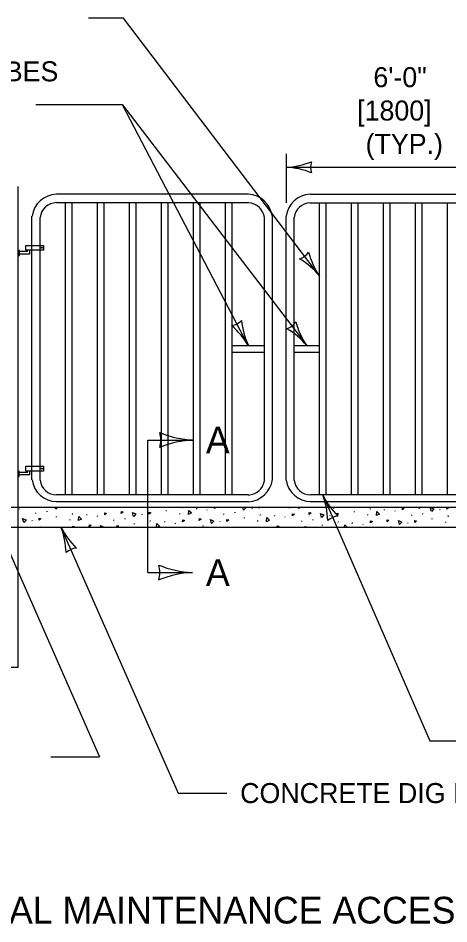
# Model space of a CAD drawing. Extents: x 49991.4 to 50021, y 49987.6 to 50011.4.
# Drawn here: x 50001.949 to 50003.24, y 49992.169 to 49994.882 of the extents above; entities that cross this region are included whole.
import ezdxf

# ---------------------------------------------------------------- set-up
doc = ezdxf.new("R2010")
doc.units = 0
for name, color, linetype in [('Level 1', 7, 'Continuous'), ('Level 2', 7, 'Continuous'), ('Level 3', 7, 'Continuous'), ('Level 4', 7, 'Continuous'), ('Level 6', 7, 'Continuous')]:
    doc.layers.add(name, color=color, linetype=linetype)

msp = doc.modelspace()

# ---------------------------------------------------------------- linework, layer by layer
at = {"layer": 'Level 1'}
for p, q in [((50001.9492, 49993.4177), (50001.9492, 49994.3778)), ((50002.639, 49994.3543), (50002.0642, 49994.3544)), ((50002.8238, 49994.3543), (50003.3985, 49994.3543)), ((50002.6391, 49994.3293), (50002.0641, 49994.3293)), ((50002.0908, 49993.4537), (50002.0908, 49994.3293)), ((50002.1108, 49993.4537), (50002.1108, 49994.3293)), ((50002.1868, 49993.4537), (50002.1868, 49994.3293)), ((50002.2068, 49993.4537), (50002.2068, 49994.3293)), ((50002.2828, 49993.4537), (50002.2828, 49994.3293)), ((50002.3028, 49993.4537), (50002.3028, 49994.3293)), ((50002.3788, 49993.4537), (50002.3788, 49994.3293)), ((50002.3988, 49993.4537), (50002.3988, 49994.3293)), ((50002.4748, 49993.4537), (50002.4748, 49994.3293)), ((50002.4948, 49993.4537), (50002.4948, 49994.3293)), ((50002.5708, 49993.4537), (50002.5708, 49994.3293)), ((50002.5908, 49993.4537), (50002.5908, 49994.3293)), ((50002.8236, 49994.3293), (50003.3985, 49994.3293)), ((50002.8519, 49993.4537), (50002.8519, 49994.3293)), ((50002.8719, 49993.4537), (50002.8719, 49994.3293)), ((50002.9479, 49993.4537), (50002.9479, 49994.3293)), ((50002.9679, 49993.4537), (50002.9679, 49994.3293)), ((50003.0439, 49993.4537), (50003.0439, 49994.3293)), ((50003.0639, 49993.4537), (50003.0639, 49994.3293)), ((50003.1399, 49993.4537), (50003.1399, 49994.3293)), ((50003.1599, 49993.4537), (50003.1599, 49994.3293)), ((50003.2359, 49993.4537), (50003.2359, 49994.3293)), ((50001.9908, 49993.4993), (50001.9908, 49994.2888)), ((50002.0148, 49993.4978), (50002.0148, 49994.2853)), ((50002.6868, 49993.4957), (50002.6868, 49994.2853)), ((50002.7108, 49993.4999), (50002.7108, 49994.2888)), ((50002.7519, 49993.4986), (50002.7519, 49994.2888)), ((50002.7759, 49993.498), (50002.7759, 49994.2853)), ((50001.9722, 49994.1866), (50001.9722, 49994.2014)), ((50001.9722, 49994.2014), (50002.0252, 49994.2014)), ((50002.0252, 49994.2014), (50002.0252, 49994.1866)), ((50001.953, 49994.1864), (50001.9492, 49994.1864)), ((50001.9773, 49994.1827), (50001.9492, 49994.1827)), ((50001.9848, 49994.1752), (50001.9492, 49994.1752)), ((50001.9492, 49994.171), (50001.953, 49994.171)), ((50001.953, 49994.171), (50001.953, 49994.1864)), ((50002.0252, 49994.1866), (50001.9722, 49994.1866)), ((50001.9773, 49994.1827), (50001.9773, 49994.1866)), ((50001.9848, 49994.1752), (50001.9848, 49994.1866)), ((50002.5908, 49993.9015), (50002.6868, 49993.9015)), ((50002.7759, 49993.9015), (50002.8519, 49993.9015)), ((50002.5908, 49993.8815), (50002.6868, 49993.8815)), ((50002.7759, 49993.8815), (50002.8519, 49993.8815)), ((50001.9773, 49993.5211), (50001.9492, 49993.5211)), ((50001.9773, 49993.5211), (50001.9773, 49993.525)), ((50001.9848, 49993.5136), (50001.9848, 49993.525)), ((50001.9848, 49993.5136), (50001.9492, 49993.5136)), ((50002.6389, 49993.4537), (50002.0641, 49993.4537)), ((50003.4, 49993.4537), (50002.8253, 49993.4537)), ((49999.9385, 49993.4177), (50005.4753, 49993.4177)), ((50001.952, 49993.4125), (50001.9533, 49993.4116)), ((50002.6389, 49993.4337), (50002.0642, 49993.4337)), ((50002.0862, 49993.4177), (50002.0872, 49993.416)), ((50002.332, 49993.4168), (50002.3321, 49993.4177)), ((50002.4397, 49993.416), (50002.441, 49993.4151)), ((50002.4407, 49993.4159), (50002.442, 49993.415)), ((50002.4844, 49993.4117), (50002.4844, 49993.4139)), ((50002.6489, 49993.4145), (50002.6499, 49993.4127)), ((50002.7633, 49993.4145), (50002.7634, 49993.4167)), ((50003.4, 49993.4337), (50002.8253, 49993.4337)), ((50002.8947, 49993.4136), (50002.8948, 49993.4158)), ((50003.0024, 49993.4128), (50003.0037, 49993.4119)), ((50003.0034, 49993.4127), (50003.0047, 49993.4118)), ((50003.2116, 49993.4112), (50003.2126, 49993.4095)), ((50002.0028, 49993.3986), (50002.0028, 49993.4007)), ((50002.0366, 49993.403), (50002.0366, 49993.4051)), ((50002.0644, 49993.3873), (50002.0644, 49993.3895)), ((50002.1105, 49993.3978), (50002.1118, 49993.3969)), ((50002.1114, 49993.3976), (50002.1127, 49993.3968)), ((50002.1551, 49993.3935), (50002.1552, 49993.3956)), ((50002.1854, 49993.391), (50002.1867, 49993.3902)), ((50002.3196, 49993.3962), (50002.3206, 49993.3945)), ((50002.3937, 49993.4056), (50002.3937, 49993.4077)), ((50002.4341, 49993.3963), (50002.4341, 49993.3984)), ((50002.5147, 49993.4093), (50002.516, 49993.4084)), ((50002.5655, 49993.3954), (50002.5655, 49993.3975)), ((50002.5993, 49993.3998), (50002.5993, 49993.4019)), ((50002.6271, 49993.3841), (50002.6271, 49993.3863)), ((50002.6732, 49993.3945), (50002.6745, 49993.3937)), ((50002.6742, 49993.3944), (50002.6755, 49993.3936)), ((50002.7178, 49993.3903), (50002.7179, 49993.3924)), ((50002.7481, 49993.3878), (50002.7494, 49993.387)), ((50002.9564, 49993.4024), (50002.9564, 49993.4045)), ((50002.9968, 49993.3931), (50002.9968, 49993.3952)), ((50003.0471, 49993.4085), (50003.0472, 49993.4107)), ((50003.0774, 49993.4061), (50003.0787, 49993.4052)), ((50003.1282, 49993.3922), (50003.1282, 49993.3943)), ((50003.162, 49993.3966), (50003.162, 49993.3987)), ((50003.2359, 49993.3913), (50003.2372, 49993.3905)), ((50003.2369, 49993.3912), (50003.2382, 49993.3903)), ((50001.8892, 49993.3577), (50003.5733, 49993.3577)), ((50001.9904, 49993.378), (50001.9913, 49993.3763)), ((50002.0146, 49993.3581), (50002.0151, 49993.3577)), ((50002.0156, 49993.3579), (50002.0159, 49993.3577)), ((50002.1048, 49993.378), (50002.1049, 49993.3802)), ((50002.2362, 49993.3771), (50002.2363, 49993.3793)), ((50002.27, 49993.3815), (50002.2701, 49993.3837)), ((50002.2978, 49993.3659), (50002.2979, 49993.368)), ((50002.3383, 49993.3577), (50002.3383, 49993.3587)), ((50002.3439, 49993.3763), (50002.3452, 49993.3754)), ((50002.3449, 49993.3762), (50002.3462, 49993.3753)), ((50002.3886, 49993.372), (50002.3886, 49993.3742)), ((50002.4189, 49993.3696), (50002.4202, 49993.3687)), ((50002.4697, 49993.3577), (50002.4697, 49993.3578)), ((50002.5034, 49993.3601), (50002.5035, 49993.3622)), ((50002.5531, 49993.3748), (50002.554, 49993.373)), ((50002.6675, 49993.3748), (50002.6676, 49993.377)), ((50002.7989, 49993.3739), (50002.799, 49993.3761)), ((50002.8327, 49993.3783), (50002.8328, 49993.3805)), ((50002.8605, 49993.3627), (50002.8606, 49993.3648)), ((50002.9066, 49993.3731), (50002.9079, 49993.3722)), ((50002.9076, 49993.373), (50002.9089, 49993.3721)), ((50002.9513, 49993.3688), (50002.9513, 49993.371)), ((50002.9816, 49993.3664), (50002.9829, 49993.3655)), ((50003.0662, 49993.3577), (50003.0662, 49993.359)), ((50003.1158, 49993.3716), (50003.1167, 49993.3698)), ((50003.1898, 49993.3809), (50003.1899, 49993.383)), ((50003.2302, 49993.3716), (50003.2303, 49993.3737))]:
    msp.add_line(p, q, dxfattribs=at)
for points in [[(50001.9492, 49993.5248), (50001.9492, 49993.5093), (50001.9528, 49993.5093), (50001.9528, 49993.5248)], [(50001.9722, 49993.525), (50001.9722, 49993.5397), (50002.0252, 49993.5397), (50002.0252, 49993.525)]]:
    msp.add_lwpolyline(points, close=True, dxfattribs=at)
for points in [[(50001.9752, 49993.416), (50001.9753, 49993.4177)], [(50001.9772, 49993.4177), (50001.9752, 49993.416)], [(50002.0618, 49993.411), (50002.06, 49993.4177)], [(50002.068, 49993.4177), (50002.0619, 49993.4112)], [(50002.1077, 49993.4175), (50002.1077, 49993.4177)], [(50002.108, 49993.4177), (50002.1077, 49993.4175)], [(50002.2262, 49993.4166), (50002.2263, 49993.4177)], [(50002.2284, 49993.4177), (50002.2264, 49993.4167)], [(50002.5379, 49993.4128), (50002.5381, 49993.4177)], [(50002.5423, 49993.4177), (50002.5434, 49993.4174), (50002.5379, 49993.4128)], [(50002.5876, 49993.4167), (50002.5877, 49993.4177)], [(50002.5889, 49993.4177), (50002.5876, 49993.4167)], [(50002.6245, 49993.4078), (50002.6219, 49993.4177)], [(50002.6263, 49993.4177), (50002.6315, 49993.4155), (50002.6246, 49993.4079)], [(50002.6704, 49993.4142), (50002.6706, 49993.4177)], [(50002.6746, 49993.4177), (50002.6704, 49993.4142)], [(50002.7889, 49993.4134), (50002.7893, 49993.4177)], [(50002.7973, 49993.4177), (50002.7891, 49993.4135)], [(50003.1006, 49993.4096), (50003.1009, 49993.4156), (50003.1061, 49993.4142), (50003.1006, 49993.4096)], [(50003.1504, 49993.4134), (50003.1506, 49993.4177)], [(50003.1555, 49993.4177), (50003.1504, 49993.4134)], [(50003.1872, 49993.4046), (50003.184, 49993.4167), (50003.1943, 49993.4122), (50003.1873, 49993.4047)], [(50003.2331, 49993.411), (50003.2334, 49993.417), (50003.2387, 49993.4157), (50003.2331, 49993.411)], [(50002.0119, 49993.3778), (50002.0122, 49993.3838), (50002.0174, 49993.3824), (50002.0119, 49993.3778)], [(50002.1304, 49993.3769), (50002.1315, 49993.3893), (50002.1396, 49993.3817), (50002.1306, 49993.377)], [(50002.2086, 49993.3945), (50002.2089, 49993.4005), (50002.2142, 49993.3992), (50002.2086, 49993.3945)], [(50002.2584, 49993.3984), (50002.2587, 49993.4044), (50002.2639, 49993.4031), (50002.2584, 49993.3984)], [(50002.2952, 49993.3896), (50002.292, 49993.4016), (50002.3023, 49993.3972), (50002.2954, 49993.3897)], [(50002.3411, 49993.396), (50002.3415, 49993.402), (50002.3467, 49993.4007), (50002.3411, 49993.396)], [(50002.4596, 49993.3951), (50002.4608, 49993.4076), (50002.4689, 49993.3999), (50002.4598, 49993.3952)], [(50002.6931, 49993.3737), (50002.6942, 49993.3861), (50002.7023, 49993.3785), (50002.6933, 49993.3738)], [(50002.7713, 49993.3913), (50002.7716, 49993.3973), (50002.7769, 49993.396), (50002.7713, 49993.3913)], [(50002.8211, 49993.3952), (50002.8214, 49993.4012), (50002.8267, 49993.3999), (50002.8211, 49993.3952)], [(50002.8579, 49993.3863), (50002.8548, 49993.3984), (50002.865, 49993.394), (50002.8581, 49993.3865)], [(50002.9038, 49993.3928), (50002.9042, 49993.3988), (50002.9094, 49993.3974), (50002.9038, 49993.3928)], [(50003.0223, 49993.3919), (50003.0235, 49993.4044), (50003.0316, 49993.3967), (50003.0225, 49993.392)], [(50001.9659, 49993.3713), (50001.9628, 49993.3834), (50001.973, 49993.379), (50001.9661, 49993.3715)], [(50002.1129, 49993.3577), (50002.1131, 49993.3608), (50002.1183, 49993.3595), (50002.1162, 49993.3577)], [(50002.1625, 49993.3587), (50002.1629, 49993.3647), (50002.1681, 49993.3634), (50002.1625, 49993.3587)], [(50002.1973, 49993.3577), (50002.1962, 49993.3619), (50002.206, 49993.3577)], [(50002.2454, 49993.3577), (50002.2456, 49993.3623), (50002.2509, 49993.361), (50002.247, 49993.3577)], [(50002.364, 49993.3577), (50002.365, 49993.3679), (50002.3731, 49993.3602), (50002.3682, 49993.3577)], [(50002.442, 49993.3731), (50002.4424, 49993.3791), (50002.4476, 49993.3777), (50002.442, 49993.3731)], [(50002.4918, 49993.377), (50002.4921, 49993.383), (50002.4974, 49993.3816), (50002.4918, 49993.377)], [(50002.5286, 49993.3681), (50002.5255, 49993.3802), (50002.5357, 49993.3758), (50002.5288, 49993.3682)], [(50002.5746, 49993.3746), (50002.5749, 49993.3805), (50002.5801, 49993.3792), (50002.5746, 49993.3746)], [(50002.7254, 49993.3577), (50002.7256, 49993.3615), (50002.7308, 49993.3602), (50002.7279, 49993.3577)], [(50002.7592, 49993.3577), (50002.7589, 49993.3587), (50002.7613, 49993.3577)], [(50002.8083, 49993.3577), (50002.8083, 49993.3591), (50002.8136, 49993.3577), (50002.8135, 49993.3577)], [(50002.927, 49993.3577), (50002.9277, 49993.3647), (50002.935, 49993.3577)], [(50003.0047, 49993.3699), (50003.0051, 49993.3759), (50003.0103, 49993.3745), (50003.0047, 49993.3699)], [(50003.0545, 49993.3737), (50003.0548, 49993.3797), (50003.0601, 49993.3784), (50003.0545, 49993.3737)], [(50003.0913, 49993.3649), (50003.0882, 49993.377), (50003.0984, 49993.3725), (50003.0915, 49993.365)], [(50003.1373, 49993.3713), (50003.1376, 49993.3773), (50003.1429, 49993.376), (50003.1373, 49993.3713)]]:
    msp.add_lwpolyline(points, dxfattribs=at)
for centre in [(50002.0202, 49994.1943), (50002.0202, 49993.5327)]:
    msp.add_circle(centre, 0.00125, dxfattribs=at)
for centre, radius, start, end in [((50002.0663, 49994.2782), 0.0762, 91.5229, 171.9742), ((50002.6353, 49994.2782), 0.0762, 8.0258, 87.2614), ((50002.8274, 49994.2782), 0.0762, 92.7386, 171.9742), ((50002.0655, 49994.2782), 0.0512, 91.5229, 171.9742), ((50002.6361, 49994.2782), 0.0512, 8.0258, 86.6578), ((50002.8266, 49994.2782), 0.0512, 93.3422, 171.9742), ((50002.0663, 49993.5099), 0.0762, 188.0258, 268.4771), ((50002.0655, 49993.5049), 0.0512, 188.0258, 268.4771), ((50002.6352, 49993.5098), 0.0762, 272.7386, 352.5107), ((50002.6364, 49993.5048), 0.0512, 272.7386, 349.801), ((50002.8273, 49993.5099), 0.0762, 188.5288, 268.4771), ((50002.8266, 49993.5049), 0.0512, 187.7401, 268.4771)]:
    msp.add_arc(centre, radius, start, end, dxfattribs=at)
at = {"layer": 'Level 3'}
for p, q in [((50002.2652, 49994.8821), (50002.1604, 49994.8821)), ((50002.8519, 49994.1104), (50002.2652, 49994.8821)), ((50002.2624, 49994.6227), (50002.0021, 49994.6227)), ((50002.6388, 49993.9015), (50002.2624, 49994.6227)), ((50002.2624, 49994.6227), (50002.8139, 49993.9015)), ((50002.7519, 49994.4753), (50002.7519, 49994.3288)), ((50002.7519, 49994.4353), (50003.472, 49994.4353)), ((50002.8617, 49993.4537), (50003.1823, 49992.7172)), ((50002.8824, 49993.393), (50002.8833, 49993.3913)), ((50001.8892, 49993.3577), (50002.1928, 49992.6694)), ((50002.0775, 49993.3577), (50002.429, 49992.5608)), ((50003.1823, 49992.7172), (50003.3277, 49992.7172)), ((50002.0474, 49992.6694), (50002.1928, 49992.6694)), ((50002.429, 49992.5608), (50002.5744, 49992.5608))]:
    msp.add_line(p, q, dxfattribs=at)
for centre, radius, start, end in [((50002.7404, 49994.668), 0.233, 272.8273, 292.0772), ((50002.8801, 49994.4353), 0.0548, 162.1388, 197.8612), ((50002.7428, 49994.2132), 0.2223, 67.456, 87.6395), ((50002.7743, 49994.2125), 0.0548, 289.3851, 325.1074), ((50003.0343, 49994.2375), 0.2223, 194.7022, 214.8858), ((50002.6736, 49993.9604), 0.233, 40.0735, 59.3234), ((50002.5795, 49994.0151), 0.0548, 279.7009, 315.4232), ((50002.4378, 49993.7836), 0.233, 30.3893, 49.6392), ((50002.84, 49993.9961), 0.2223, 185.018, 205.2016), ((50002.736, 49994.0033), 0.0548, 289.5454, 325.2678), ((50002.9959, 49994.0291), 0.2223, 194.8626, 215.0461), ((50002.6361, 49993.751), 0.233, 40.2339, 59.4838), ((50002.487, 49993.9146), 0.2964, 247.456, 267.6395), ((50002.3039, 49993.6184), 0.073, 342.1388, 17.8612), ((50002.4901, 49993.3082), 0.3107, 92.8273, 112.0772), ((50002.6544, 49993.3735), 0.2223, 0.9771, 21.1606), ((50003.0705, 49993.5571), 0.233, 206.3484, 225.5982), ((50002.9129, 49993.3362), 0.0548, 95.6599, 131.3822), ((50001.8706, 49993.2765), 0.2223, 1.2527, 21.4362), ((50002.2858, 49993.4621), 0.233, 206.624, 225.8739), ((50002.1293, 49993.2404), 0.0548, 95.9355, 131.6579), ((50002.484, 49993.5176), 0.2964, 247.456, 267.6395), ((50002.3009, 49993.2214), 0.073, 342.1388, 17.8612), ((50002.4871, 49992.9112), 0.3107, 92.8273, 112.0772)]:
    msp.add_arc(centre, radius, start, end, dxfattribs=at)
at = {"layer": 'Level 4'}
for p, q in [((50001.9492, 49992.9377), (50001.9492, 49993.4177)), ((50001.8892, 49992.9377), (50001.9492, 49992.9377))]:
    msp.add_line(p, q, dxfattribs=at)
at = {"layer": 'Level 6'}
for p, q in [((50002.3379, 49993.2214), (50002.3379, 49993.6184)), ((50002.3379, 49993.6184), (50002.4718, 49993.6184)), ((50002.3379, 49993.2214), (50002.4718, 49993.2214))]:
    msp.add_line(p, q, dxfattribs=at)

# ---------------------------------------------------------------- texts
at = {"layer": 'Level 2'}
for s, height, p in [('HORIZONTAL TUBES', 0.06, (50001.2629, 49994.6927)), ('6\'-0"', 0.06, (50003.0135, 49994.6753)), ('[1800]', 0.06, (50002.9648, 49994.5753)), ('(TYP.)', 0.06, (50002.9901, 49994.4753)), ('A', 0.08, (50002.5118, 49993.5784)), ('A', 0.08, (50002.5118, 49993.1814)), ('CONCRETE DIG BARRIER APRON', 0.060003, (50002.6144, 49992.5308)), ('METAL MAINTENANCE ACCESS GATE', 0.08, (50001.696, 49992.1701))]:
    msp.add_text(s, height=height, dxfattribs=at).set_placement(p)

doc.saveas('drawing.dxf')
